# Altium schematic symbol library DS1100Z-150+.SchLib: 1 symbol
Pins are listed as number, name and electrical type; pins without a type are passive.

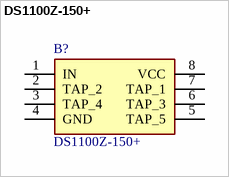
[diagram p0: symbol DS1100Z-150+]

## DS1100Z-150+
designator B?
Delay Lines / Timing Elements 5-Tap Economy Timing Element (Delay Line); Manufacturer_Name: Analog Devices; Geometry.Height: 1.75mm
footprint SOIC127P600X175-8N
pins: 1 IN, 2 TAP_2, 3 TAP_4, 4 GND, 5 TAP_5, 6 TAP_3, 7 TAP_1, 8 VCC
